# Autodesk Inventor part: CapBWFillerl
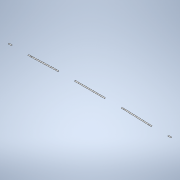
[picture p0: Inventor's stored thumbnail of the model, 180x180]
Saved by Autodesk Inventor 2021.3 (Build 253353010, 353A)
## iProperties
Created: 2021-11
Part Number: CapBWFillerl
Material: Polystyrene, High Impact
Document SubType Name: Modeling
Designer: u1426
Density: 1.022 g/cm^3
Appearance: Smooth - White
Author: u1426
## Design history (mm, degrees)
sketch "Sketch1"
  geometry: L1 (-3962.4, 0)-(-2336.8, 60.96); L2 (2336.8, 60.96)-(3962.4, 0); L3 (3962.519, 6.35)-(2336.919, 67.31); L4 (-2336.919, 67.31)-(-3962.519, 6.35); L5 (5486.4, 0)-(5486.4, 6.35); L6 (-5486.4, 0)-(-5486.4, 6.35); L7 (-4724.4, 340.555)-(-4724.4, -290.397); L8 (-1574.8, 209.871)-(-1574.8, -290.397); L9 (1574.8, 198.637)-(1574.8, -375.937); L10 (4724.4, 198.637)-(4724.4, -290.397); L11 (-5283.2, 6.35)-(-5283.2, 0); L12 (-4165.6, 6.35)-(-4165.6, 0); L13 (-2133.6, 67.31)-(-2133.6, 60.96); L14 (-1016, 67.31)-(-1016, 60.96); L15 (2133.6, 67.31)-(2133.6, 60.96); L16 (1016, 67.31)-(1016, 60.96); L17 (5283.2, 6.35)-(5283.2, 0); L18 (4165.6, 6.35)-(4165.6, 0); L19 (5486.4, 0)-(5283.2, 0); L20 (4165.6, 0)-(3962.4, 0); L21 (5486.4, 6.35)-(5283.2, 6.35); L22 (4165.6, 6.35)-(3962.519, 6.35); L23 (2133.6, 60.96)-(2336.8, 60.96); L24 (2336.919, 67.31)-(2133.6, 67.31); L25 (-2336.8, 60.96)-(-2133.6, 60.96); L26 (-1016, 60.96)-(1016, 60.96); L27 (1016, 67.31)-(-1016, 67.31); L28 (-2133.6, 67.31)-(-2336.919, 67.31); L29 (-5486.4, 0)-(-5283.2, 0); L30 (-4165.6, 0)-(-3962.4, 0); L31 (-3962.519, 6.35)-(-4165.6, 6.35); L32 (-5283.2, 6.35)-(-5486.4, 6.35); 1 further point
  constraints: 64 end point, 26 perpendicular, 8 collinear, 5 horizontal, 4 vertical
  dimensions: "d4" = 1524 distance of L5.start L2.end; "d5" = 1524 distance of L6.start L1.start; "d6" = 1625.6 horizontal distance of L2.start L2.end; "d7" = 1625.6 horizontal distance of L1.start L1.end; "d8" = 4673.6 distance of L1.end L2.start (derived); "d9" = 2336.8 horizontal distance of L1.end point (0, 0) (derived); "d10" = 60.96 vertical distance of L1.start L1.end; "d52" = 5486.4 distance from line of L6 point (0, 0); "d54" = 762 distance between parallel lines of L7 L6; "d55" = 3149.6 distance between parallel lines of L8 L7; "d56" = 3149.6 distance between parallel lines of L9 L8; "d57" = 3149.6 distance between parallel lines of L10 L9; "d59" = 5486.4 distance from line of L5 point (0, 0); "d60" = 762 distance from line of L5.start L10 (derived); "d61" = 558.8 distance between parallel lines of L11 L7; "d62" = 558.8 distance between parallel lines of L12 L7; "d63" = 558.8 distance between parallel lines of L13 L8; "d64" = 558.8 distance between parallel lines of L14 L8; "d65" = 558.8 distance between parallel lines of L16 L9; "d66" = 558.8 distance between parallel lines of L15 L9; "d67" = 558.8 distance between parallel lines of L18 L10; "d68" = 558.8 distance between parallel lines of L17 L10; "d69" = 60.96 distance from line of point (0, 0) L26; "d70" = 6.35 distance between parallel lines of L27 L26; "d71" = 60.96 distance from line of point (0, 0) L25; "d72" = 6.35 distance between parallel lines of L4 L1; "d73" = 6.35 distance between parallel lines of L28 L25; "d74" = 6.35 distance between parallel lines of L31 L30; "d75" = 60.96 distance from line of point (0, 0) L23; "d76" = 6.35 distance between parallel lines of L24 L23; "d77" = 6.35 distance between parallel lines of L3 L2
extrude "Extrusion1" new body sketch "Sketch1" distance "d11" = 76.2; taper "d12" = 0 deg
body "Solid1"
other parameters: "d51" = 6.35, "d53" = 0
